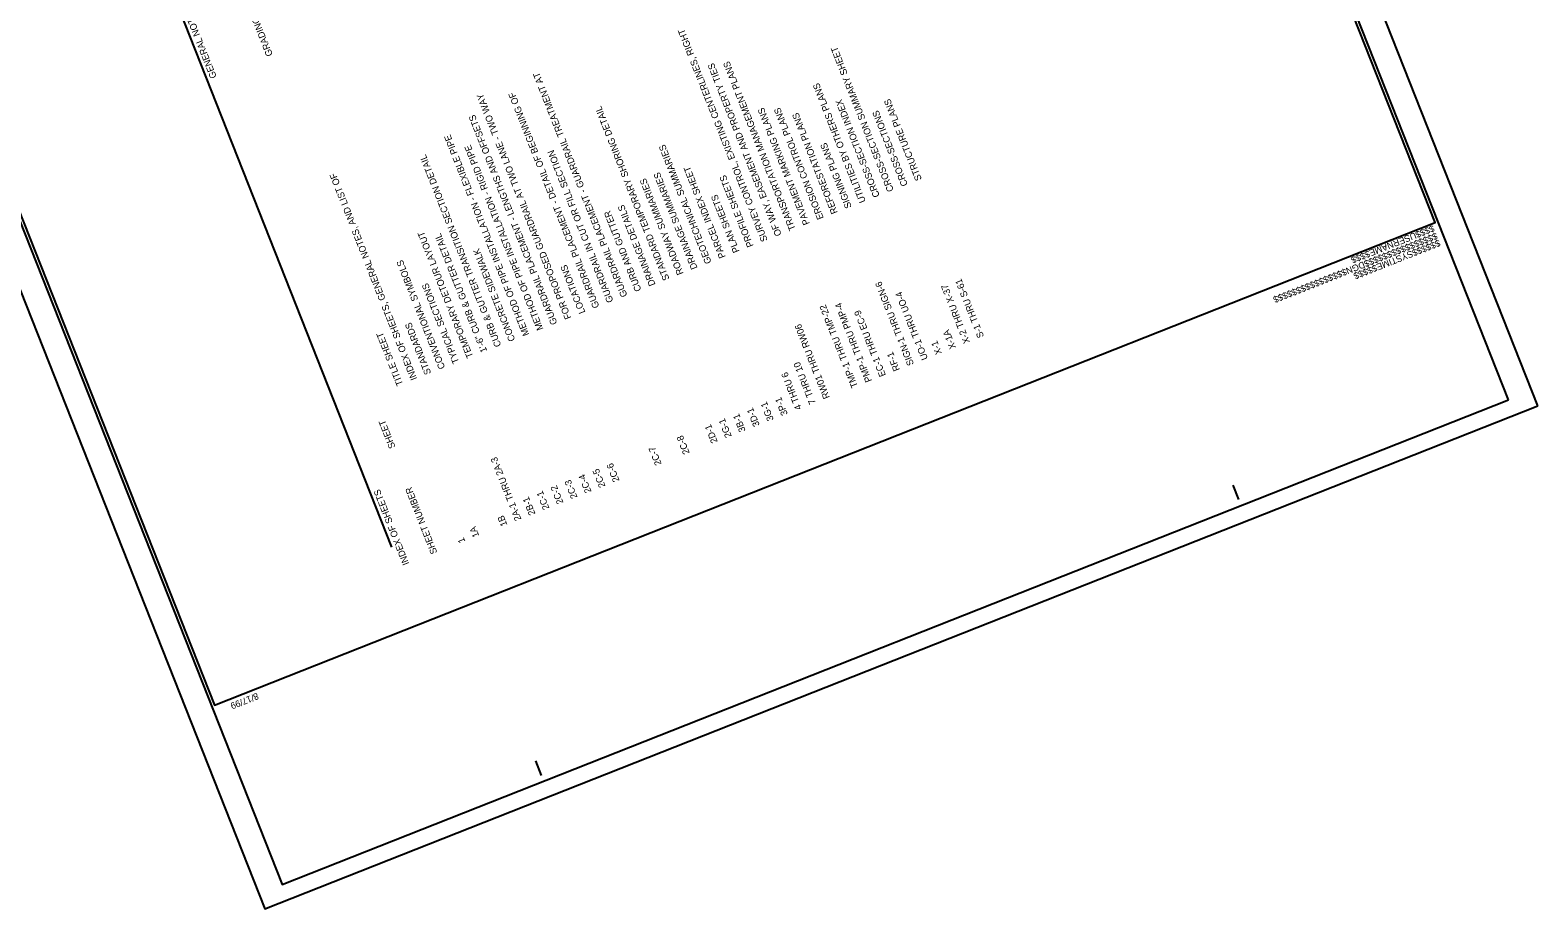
# Model space of a CAD drawing. Extents: x 1247235 to 1260080, y 742320 to 754020.
# Drawn here: x 1254628 to 1260080, y 745123 to 748302 of the extents above; entities that cross this region are included whole.
import ezdxf

# ---------------------------------------------------------------- set-up
doc = ezdxf.new("R2010")
doc.units = 0
for name, color, linetype in [('Scratch_Level_2', 7, 'Continuous'), ('Sheet Data Text CELL', 7, 'Continuous'), ('Sheet Plan CELL', 7, 'Continuous'), ('Sheet Plot Border Inside CELL', 7, 'Continuous'), ('Sheet Plot Border Outside CELL', 7, 'Continuous')]:
    doc.layers.add(name, color=color, linetype=linetype)

msp = doc.modelspace()

# ---------------------------------------------------------------- linework, layer by layer
at = {"layer": 'Scratch_Level_2'}
msp.add_line((1255936.1, 746431.7), (1253258.3, 753203.9), dxfattribs=at)
at = {"layer": 'Sheet Plan CELL'}
for p, q in [((1259708.5, 747605.8), (1259708.5, 747605.8)), ((1258999, 746603.4), (1258978.2, 746655.9)), ((1255294.6, 745860.4), (1255294.6, 745860.4)), ((1256476.7, 745606), (1256456, 745658.6))]:
    msp.add_line(p, q, dxfattribs=at)
msp.add_lwpolyline([(1252801.2, 752166.1), (1255294.6, 745860.4), (1259708.5, 747605.8), (1257215.2, 753911.5)], close=True, dxfattribs=at)
at = {"layer": 'Sheet Plot Border Inside CELL'}
msp.add_lwpolyline([(1259974.2, 746964.6), (1257204.9, 753968.2), (1252769.9, 752214.5), (1255539.2, 745211)], close=True, dxfattribs=at)
at = {"layer": 'Sheet Plot Border Outside CELL'}
msp.add_lwpolyline([(1260079.9, 746943.2), (1257281.5, 754020.3), (1252678.4, 752200.2), (1255476.7, 745123.1)], close=True, dxfattribs=at)

# ---------------------------------------------------------------- texts
at = {"layer": 'Sheet Data Text CELL'}
for s, height, p in [('GRADING AND SURFACING OR RESURFACING AND WIDENING:  ', 24.23, (1255505.6, 748212.4)), ('GENERAL NOTES:                         2024 SPECIFICATIONS', 24.23, (1255302.8, 748132.2)), ('SURVEY CONTROL, EXISTING CENTERLINES, RIGHT ', 24.23, (1257295, 747541.8)), ('CROSS-SECTION SUMMARY SHEET', 24.23, (1257751.3, 747722.2)), ('OF WAY, EASEMENT AND PROPERTY TIES', 24.23, (1257345.7, 747561.9)), ('TRANSPORTATION MANAGEMENT PLANS', 24.23, (1257396.4, 747581.9)), ('GUARDRAIL PLACEMENT - GUARDRAIL TREATMENT AT ', 24.23, (1256788, 747341.4)), ('FOR PROPOSED GUARDRAIL AT TWO LANE - TWO WAY ', 24.23, (1256585.2, 747261.2)), ('GUARDRAIL PLACEMENT - DETAIL OF BEGINNING OF ', 24.23, (1256686.6, 747301.3)), ('UTILITIES BY OTHERS PLANS', 24.23, (1257649.9, 747682.2)), ('STANDARD TEMPORARY SHORING DETAIL', 24.23, (1256940.1, 747401.5)), ('PAVEMENT MARKING PLANS', 24.23, (1257447.1, 747602)), ('EROSION CONTROL PLANS', 24.23, (1257497.8, 747622)), ('CROSS-SECTION INDEX', 24.23, (1257700.6, 747702.2)), ('CROSS-SECTIONS', 24.23, (1257802, 747742.3)), ('STRUCTURE PLANS', 24.23, (1257852.7, 747762.3)), ('GUARDRAIL PLACEMENT - LENGTHS AND OFFSETS ', 24.23, (1256534.5, 747241.1)), ('REFORESTATION PLANS', 24.23, (1257548.5, 747642.1)), ('METHOD OF PIPE INSTALLATION - FLEXIBLE PIPE', 24.23, (1256433.1, 747201)), ('CURB & GUTTER TRANSITION SECTION DETAIL', 24.23, (1256331.7, 747160.9)), ('METHOD OF PIPE INSTALLATION - RIGID PIPE', 24.23, (1256483.8, 747221.1)), ('GUARDRAIL IN CUT OR FILL SECTION', 24.23, (1256737.3, 747321.3)), ('GEOTECHNICAL SUMMARIES', 24.23, (1257092.2, 747461.6)), ('SIGNING PLANS', 24.23, (1257599.2, 747662.1)), ('PARCEL INDEX SHEET', 24.23, (1257142.9, 747481.7)), ('INDEX OF SHEETS, GENERAL NOTES, AND LIST OF ', 24.23, (1256027.5, 747040.6)), ('ROADWAY SUMMARIES', 24.23, (1256990.8, 747421.5)), ('DRAINAGE SUMMARIES', 24.23, (1257041.5, 747441.6)), ('PROFILE SHEETS', 24.23, (1257244.3, 747521.8)), ('PLAN SHEETS', 24.23, (1257193.6, 747501.7)), ('CURB AND GUTTER', 24.23, (1256838.7, 747361.4)), ('DRAINAGE DETAILS', 24.23, (1256889.4, 747381.4)), ('TEMPORARY DETOUR LAYOUT', 24.23, (1256230.3, 747120.8)), ('1\'-6" CURB & GUTTER DETAIL', 24.23, (1256281, 747140.9)), ('CONVENTIONAL SYMBOLS  ', 24.23, (1256128.9, 747080.7)), ('CONCRETE SIDEWALK', 24.23, (1256382.4, 747181)), ('LOCATIONS', 24.23, (1256635.9, 747281.2)), ('TYPICAL SECTIONS', 24.23, (1256179.6, 747100.8)), ('SIGN-1 THRU SIGN-6', 24.23, (1257824.1, 747093.4)), ('UO-1 THRU UO-4', 24.23, (1257874.8, 747113.5)), ('X-2 THRU X-37', 24.23, (1258026.9, 747173.6)), ('S-1 THRU S-61', 24.23, (1258077.6, 747193.7)), ('TMP-1 THRU TMP-22', 24.23, (1257621.3, 747013.3)), ('PMP-1 THRU PMP-4 ', 24.23, (1257672, 747033.3)), ('STANDARDS', 24.23, (1256078.2, 747060.7)), ('EC-1 THRU EC-9', 24.23, (1257722.7, 747053.4)), ('TITLE SHEET ', 24.23, (1255976.8, 747020.6)), ('RW01 THRU RW06', 24.23, (1257519.9, 746973.2)), ('X-1A', 24.23, (1257976.2, 747153.6)), ('RF-1', 24.23, (1257773.4, 747073.4)), ('X-1', 24.23, (1257925.5, 747133.5)), ('7 THRU 10', 24.23, (1257469.2, 746953.1)), ('4 THRU 6', 24.23, (1257418.5, 746933.1)), ('3P-1', 24.23, (1257367.8, 746913)), ('3D-1', 24.23, (1257266.4, 746872.9)), ('3G-1', 24.23, (1257317.1, 746893)), ('SHEET NUMBER                 SHEET   ', 24.23, (1256100.3, 746411.9)), ('2D-1', 24.23, (1257114.3, 746812.8)), ('2G-1', 24.23, (1257165, 746832.8)), ('3B-1', 24.23, (1257215.7, 746852.9)), ('2C-8', 24.23, (1257012.9, 746772.7)), ('2A-1 THRU 2A-3', 24.23, (1256404.5, 746532.1)), ('2C-7', 24.23, (1256911.5, 746732.6)), ('2C-5', 24.23, (1256708.7, 746652.4)), ('2C-6', 24.23, (1256759.4, 746672.5)), ('2C-2', 24.23, (1256556.6, 746592.3)), ('2C-3', 24.23, (1256607.3, 746612.3)), ('2C-4', 24.23, (1256658, 746632.4)), ('INDEX OF SHEETS           ', 24.23, (1255998.9, 746371.8)), ('2B-1', 24.23, (1256455.2, 746552.2)), ('2C-1', 24.23, (1256505.9, 746572.2)), ('1B', 24.23, (1256353.8, 746512.1)), ('1A', 24.23, (1256252.4, 746472)), ('1', 24.2, (1256201.7, 746451.9))]:
    msp.add_text(s, height=height, rotation=111.5743, dxfattribs=at).set_placement(p)
at = {"layer": 'Sheet Plan CELL'}
for s, height, p in [('$$$$USERNAME$$$$', 23.733, (1259700.3, 747597.3)), ('$$$$$$$$$$$$$$$$DGN$$$$$$$$$$$$$$$$', 23.733, (1259711.3, 747569.7)), ('$$$$$$SYSTIME$$$$$', 23.733, (1259721.4, 747544.3)), ('8/17/99', 23.73, (1255447.9, 745905.3))]:
    msp.add_text(s, height=height, rotation=201.5743, dxfattribs=at).set_placement(p)

doc.saveas('drawing.dxf')
